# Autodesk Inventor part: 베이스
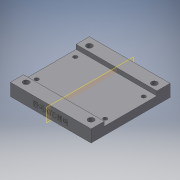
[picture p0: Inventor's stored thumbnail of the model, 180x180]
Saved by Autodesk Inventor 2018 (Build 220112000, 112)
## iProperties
Created: 2020-03
Part Number: 베이스
Material: 일반
Document SubType Name: Modeling
Designer: mduedu
Density: 2.71 g/cm^3
Mass: 221.653 g
Surface Area: 237.875 cm^2
Volume: 81.7908 cm^3
Appearance: 기본값
Author: mduedu
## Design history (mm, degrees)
sketch "스케치1"
  geometry: L1 (0, 45)-(-92, 45); L2 (-92, 45)-(-92, -45); L3 (-92, -45)-(0, -45); L4 (0, -45)-(0, 45); 2 further points
  constraints: 8 end point, 2 parallel, 1 coincident, 1 horizontal, 1 midpoint, 1 perpendicular
  dimensions: "d0" = 92 distance of L1.start L1.end; "d2" = 90 distance of L1.end L2.end
extrude "돌출1" new body sketch "스케치1" distance "d3" = 14; taper "d4" = 0 deg
sketch "스케치2"
  geometry: L1 (40, 0)-(50, 0); L2 (50, 0)-(50, 3); L3 (50, 3)-(40, 3); L4 (40, 3)-(40, 0); L5 (15, 14)-(75, 14); L6 (75, 14)-(75, 9); L7 (75, 9)-(15, 9); L8 (15, 9)-(15, 14); L9 (0, 0)-(90, 0) reference; L10 (0, 14)-(90, 14) reference; 3 further points
  constraints: 16 end point, 4 parallel, 2 collinear, 2 horizontal, 2 midpoint, 2 perpendicular, 1 vertical alignment
  dimensions: "d5" = 60 distance of L5.start L5.end; "d7" = 5 distance of L5.end L6.end; "d8" = 10 distance of L1.start L1.end; "d9" = 3 distance of L1.end L2.end
extrude "돌출2" cut sketch "스케치2" extent not by distance; stored distance "d10" = 14; taper "d11" = 0 deg
sketch "스케치3"
  geometry: L1 (9, 36)-(83, 36); L2 (83, 36)-(83, -36); L3 (83, -36)-(9, -36); L4 (9, -36)-(9, 36); L5 (92, 30)-(92, -30) reference; 2 further points
  constraints: 8 end point, 2 parallel, 1 horizontal, 1 horizontal alignment, 1 midpoint, 1 perpendicular
  dimensions: "d12" = 72 distance of L1.end L2.end; "d14" = 74 distance of L1.start L1.end; "d15" = 9 distance between parallel lines of L5 L2
hole "구멍1" sketch "스케치3" at (9, -36), (83, -36), (83, 36), (9, 36) diameter "d16" = 6.6; stored, may be unused: countersink angle "d20" = 90 deg, drill point angle "d22" = 118 deg; dims "d17" = 6, "d18" = 4, "d19" = 2, "d21" = 8
sketch "스케치4"
  geometry: L1 (7, 22)-(85, 22); L2 (85, 22)-(85, -22); L3 (85, -22)-(7, -22); L4 (7, -22)-(7, 22); L5 (0, -45)-(0, 45) reference; L6 (92, 45)-(92, -45) reference; 5 further points
  constraints: 8 end point, 2 parallel, 1 horizontal, 1 horizontal alignment, 1 midpoint, 1 perpendicular
  dimensions: "d26" = 7 distance between parallel lines of L4 L5; "d27" = 7 distance between parallel lines of L6 L2; "d28" = 44 distance of L1.end L2.end
hole "구멍2" sketch "스케치4" at (7, 22), (85, 22), (85, -22), (7, -22) diameter "d29" = 4.5; stored, may be unused: countersink angle "d33" = 90 deg, drill point angle "d35" = 118 deg; dims "d30" = 6, "d31" = 8, "d32" = 4.4, "d34" = 8
sketch "스케치5"
  geometry: L1 (0, 0)-(92, 0) reference; 5 further points
  constraints: 3 coincident, 1 midpoint, 1 vertical alignment, 1 other
  dimensions: "d36" = 7 distance of point (46, 7) point (46, 0)
feature "엠보싱1" sketch "스케치5" dims "d37" = 0.5, "d38" = 0
node "작업 평면1"
node "솔리드1"
